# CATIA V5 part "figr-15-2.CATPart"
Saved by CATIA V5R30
Part number: Part1
Bounding box of the stored display mesh (mm): x -101.427 to 121.258, y -118.645 to 66.112, z 0 to 1
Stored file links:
  D:\PROJECTS\CATIA V56R 2020\Resources\Parts File\c15_catia_v5_6r2020_prt\figr-15-2.CATPart
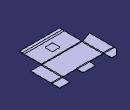
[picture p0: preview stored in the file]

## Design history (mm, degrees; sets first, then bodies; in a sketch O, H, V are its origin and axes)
SheetMetalParameters1: Thickness 1, BendRadius 2, KFactor 0.400515 {= log(min(100,max(20*SheetMetalParameters1.BendRadius,SheetMetalParameters1.Thickness)/SheetMetalParameters1.Thickness))/log(100)/2}, ReliefRadialLength 1, ReliefAxialLength 2, WallPerLength 50, MinimumBendRadius 0
Body1 (main body)
  Sketch1 on xy-plane, origin (0, 0, 0), H (1, 0, 0), V (0, 1, 0)
    line L1 (-62.6567, 37.3409) -> (82.4875, 37.3409)
    line L2 (82.4875, 37.3409) -> (82.4875, -38.1848)
    line L3 (82.4875, -38.1848) -> (-62.6567, -38.1848)
    line L4 (-62.6567, -38.1848) -> (-62.6567, 37.3409)
    horizontal: L1 H, L3 H
    vertical: L2 V, L4 V
  Wall1: Thickness 1, Profile Sketch1, OffsetValue 0
  d_NewWallOnEdge1: NewWallOnEdge_Length 25, NewWallOnEdge_HeightLimitOffset 0, NewWallOnEdge_WidthOffset1 -50, NewWallOnEdge_WidthOffset2 -50, NewWallOnEdge_Angle 90, NewWallOnEdge_BendRadiusValue 2 {= SheetMetalParameters1.BendRadius}, NewWallOnEdge_BendTable SheetMetalParameters1, NewWallOnEdge_Edge edge [face of Wall1 | face of Wall1], NewWallOnEdge_GapValue 0, KFacteur 0.400515 {= log(min(100,max(20*d_NewWallOnEdge1.Radius,SheetMetalParameters1.Thickness)/SheetMetalParameters1.Thickness))/log(100)/2}
  d_NewWallOnEdge2: NewWallOnEdge_Length 40, NewWallOnEdge_HeightLimitOffset 0, NewWallOnEdge_WidthOffset1 0, NewWallOnEdge_WidthOffset2 0, NewWallOnEdge_Angle 90, NewWallOnEdge_BendRadiusValue 2 {= SheetMetalParameters1.BendRadius}, NewWallOnEdge_BendTable SheetMetalParameters1, NewWallOnEdge_Edge edge [face of Wall1 | face of Wall1], NewWallOnEdge_GapValue 0, KFacteur 0.400515 {= log(min(100,max(20*d_NewWallOnEdge2.Radius,SheetMetalParameters1.Thickness)/SheetMetalParameters1.Thickness))/log(100)/2}
  d_NewWallOnEdge3: NewWallOnEdge_Length 30, NewWallOnEdge_HeightLimitOffset 0, NewWallOnEdge_WidthOffset1 0, NewWallOnEdge_WidthOffset2 0, NewWallOnEdge_Angle 90, NewWallOnEdge_BendRadiusValue 2 {= SheetMetalParameters1.BendRadius}, NewWallOnEdge_BendTable SheetMetalParameters1, NewWallOnEdge_Edge edge [face of d_NewWallOnEdge2 | face of d_NewWallOnEdge2], NewWallOnEdge_GapValue 0, KFacteur 0.400515 {= log(min(100,max(20*d_NewWallOnEdge3.Radius,SheetMetalParameters1.Thickness)/SheetMetalParameters1.Thickness))/log(100)/2}
  d_NewWallOnEdge4: NewWallOnEdge_Length 60, NewWallOnEdge_HeightLimitOffset 0, NewWallOnEdge_WidthOffset1 0, NewWallOnEdge_WidthOffset2 0, NewWallOnEdge_Angle 110, NewWallOnEdge_BendRadiusValue 2 {= SheetMetalParameters1.BendRadius}, NewWallOnEdge_BendTable SheetMetalParameters1, NewWallOnEdge_Edge edge [face of Wall1 | face of Wall1], NewWallOnEdge_GapValue 0, KFacteur 0.400515 {= log(min(100,max(20*d_NewWallOnEdge4.Radius,SheetMetalParameters1.Thickness)/SheetMetalParameters1.Thickness))/log(100)/2}
  Flange1: Angle 90, Length 10, Radius 2 {= SheetMetalParameters1.BendRadius}, KFacteur 0.400515 {= log(min(100,max(20*Flange1.Radius,SheetMetalParameters1.Thickness)/SheetMetalParameters1.Thickness))/log(100)/2}, Guide edge [face of d_NewWallOnEdge4 | face of d_NewWallOnEdge4]
  d_NewWallOnEdge5: NewWallOnEdge_Length 40, NewWallOnEdge_HeightLimitOffset 0, NewWallOnEdge_WidthLimit2 face of d_NewWallOnEdge4, NewWallOnEdge_WidthOffset1 0, NewWallOnEdge_WidthOffset2 -2, NewWallOnEdge_Angle 90, NewWallOnEdge_WithBend true, NewWallOnEdge_BendRadiusValue 2 {= SheetMetalParameters1.BendRadius}, NewWallOnEdge_BendTable SheetMetalParameters1, NewWallOnEdge_Edge edge [face of Wall1 | face of Wall1], NewWallOnEdge_GapValue 0, KFacteur 0.400515 {= log(min(100,max(20*d_NewWallOnEdge5.Radius,SheetMetalParameters1.Thickness)/SheetMetalParameters1.Thickness))/log(100)/2}
  d_NewWallOnEdge6: NewWallOnEdge_Length 30, NewWallOnEdge_HeightLimitOffset 0, NewWallOnEdge_WidthOffset1 0, NewWallOnEdge_WidthOffset2 0, NewWallOnEdge_Angle 90, NewWallOnEdge_BendRadiusValue 2 {= SheetMetalParameters1.BendRadius}, NewWallOnEdge_BendTable SheetMetalParameters1, NewWallOnEdge_Edge edge [face of d_NewWallOnEdge5 | face of d_NewWallOnEdge5], NewWallOnEdge_GapValue 0, KFacteur 0.400515 {= log(min(100,max(20*d_NewWallOnEdge6.Radius,SheetMetalParameters1.Thickness)/SheetMetalParameters1.Thickness))/log(100)/2}
  Chamfer1: ChamferAngle 45, ChamferLength1 20, ChamferLength2 0.5, ChamferPropagation 1, ChamferReverse false, ChamferType 1, CornerChamferEdges edge [face of d_NewWallOnEdge6 | face of d_NewWallOnEdge6]
  Corner1: CornerRadius 3, CornerChamferEdges (edge [face of d_NewWallOnEdge1 | face of d_NewWallOnEdge1]; edge [face of d_NewWallOnEdge1 | face of d_NewWallOnEdge1])
  Sketch2 on face of d_NewWallOnEdge4, origin (8.9154, -38.1848, 1), H (1, 0, 0), V (0, -0.342, 0.9397)
    line L1 (-12.2908, 45.4061) -> (12.3784, 45.4061)
    line L2 (12.3784, 45.4061) -> (12.3784, 21.719)
    line L3 (12.3784, 21.719) -> (-12.2908, 21.719)
    line L4 (-12.2908, 21.719) -> (-12.2908, 45.4061)
    horizontal: L1 H, L3 H
    vertical: L2 V, L4 V
  d_Stamp1: NewRoot_AttribNormalisation "No Standard", Stamp_FilletRadius 1, Stamp_IntersectFilletRadius 2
